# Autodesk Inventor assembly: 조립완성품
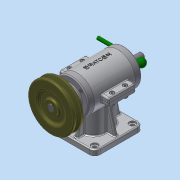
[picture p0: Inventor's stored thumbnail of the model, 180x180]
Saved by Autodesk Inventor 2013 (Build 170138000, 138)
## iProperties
Created: 2015-12
Part Number: 조립완성품
Document SubType Name: Assembly
Designer: Administrator
Mass: 1960.53 g
Surface Area: 1487.03 cm^2
Volume: 472.442 cm^3
Density: 4.14977 g/cm^3
Author: Administrator
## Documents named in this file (19)
- C:\Users\Administrator\Desktop\351208V1034\조립완성품.iam
- C:\Users\Administrator\Desktop\351208V1034\본체.ipt
- C:\Users\Administrator\Desktop\351208V1034\V-벨트풀리.ipt
- C:\Users\Administrator\Desktop\351208V1034\너트 M4.ipt
- C:\Users\Administrator\Desktop\351208V1034\뒤커버.ipt
- C:\Users\Administrator\Desktop\351208V1034\레바.ipt
- C:\Users\Administrator\Desktop\351208V1034\멈춤나사 M3x8.ipt
- C:\Users\Administrator\Desktop\351208V1034\베어링 6201.ipt
- C:\Users\Administrator\Desktop\351208V1034\베어링 6202.ipt
- C:\Users\Administrator\Desktop\351208V1034\본체커버.ipt
- C:\Users\Administrator\Desktop\351208V1034\볼트 M3x0.5x8.ipt
- C:\Users\Administrator\Desktop\351208V1034\볼트 M4 x 16.ipt
- C:\Users\Administrator\Desktop\351208V1034\슬라이드.ipt
- C:\Users\Administrator\Desktop\351208V1034\앞커버.ipt
- C:\Users\Administrator\Desktop\351208V1034\오일실 12 22 7.ipt
- C:\Users\Administrator\Desktop\351208V1034\와셔 ST 4-100.ipt
- C:\Users\Administrator\Desktop\351208V1034\키 4 x 4 x 18.ipt
- C:\Users\Administrator\Desktop\351208V1034\편심축.ipt
- C:\Users\Administrator\Desktop\351208V1034\스프링.ipt
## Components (13 placed, 4 different names)
1. V-벨트풀리:1 — 플러쉬:1
2. ISO 4032 M4:1
3. ISO 4762 M4 x 16:1
4. ISO 7091 ST 4 - 100 HV:1
5. ISO 7091 ST 4 - 100 HV:2
6. ISO 7091 ST 4 - 100 HV:3
7. ISO 7091 ST 4 - 100 HV:4
8. ISO 4032 M4:2
9. ISO 4032 M4:3
10. ISO 4032 M4:4
11. ISO 4762 M4 x 16:2
12. ISO 4762 M4 x 16:3
13. ISO 4762 M4 x 16:4
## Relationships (1: Flush 1)
- 플러쉬:1 [Flush]: V-벨트풀리:1
